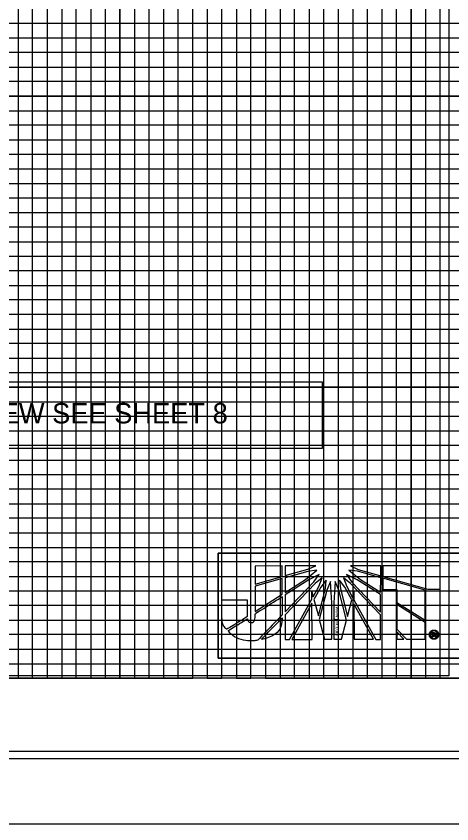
# Model space of a CAD drawing. Extents: x 557032 to 558716, y 525869 to 526969.
# Drawn here: x 558363.8 to 558513.5, y 525869.2 to 526146.7 of the extents above; entities that cross this region are included whole.
import ezdxf

# ---------------------------------------------------------------- set-up
doc = ezdxf.new("R2010")
doc.units = 0
for name, color, linetype in [('Prop VPI Label', 7, 'Continuous'), ('Scratch_Level_5', 7, 'Continuous'), ('Sheet Cutting Line CELL', 7, 'Continuous'), ('Sheet DOT Grid CELL', 7, 'Continuous'), ('Sheet Layout Profile Border Port 2', 7, 'Continuous'), ('Sheet Plot Border Inside CELL', 7, 'Continuous'), ('Sheet Plot Border Outside CELL', 7, 'Continuous'), ('Sheet Profile CELL', 7, 'Continuous'), ('Sheet Profile Grid Major CELL', 7, 'Continuous'), ('Sheet Profile Grid Middle CELL', 7, 'Continuous'), ('Sheet Profile Grid Minor CELL', 7, 'Continuous')]:
    doc.layers.add(name, color=color, linetype=linetype)

msp = doc.modelspace()

# ---------------------------------------------------------------- linework, layer by layer
at = {"layer": 'Prop VPI Label'}
for p, q in [((558455.21, 525957.82), (558445.85, 525957.81)), ((558445.85, 525957.81), (558445.85, 525951.6)), ((558455.21, 525954.21), (558455.21, 525957.82)), ((558466.72, 525957.88), (558456.18, 525957.87)), ((558456.18, 525957.87), (558456.19, 525954.51)), ((558464.03, 525956.69), (558466.72, 525957.88)), ((558489.02, 525957.85), (558478.64, 525957.89)), ((558478.64, 525957.89), (558481.27, 525956.66)), ((558489.03, 525954.48), (558489.02, 525957.85)), ((558509.43, 525957.92), (558489.75, 525957.9)), ((558489.75, 525957.9), (558489.75, 525954.28)), ((558509.44, 525949.85), (558509.43, 525957.92)), ((558445.85, 525951.6), (558455.21, 525954.21)), ((558456.19, 525954.51), (558464.03, 525956.69)), ((558464.03, 525955.96), (558456.19, 525953.79)), ((558463.22, 525953.18), (558467.09, 525956.33)), ((558467.09, 525956.33), (558464.03, 525955.96)), ((558467.86, 525954.88), (558464.3, 525953.07)), ((558466.06, 525952.35), (558467.86, 525954.88)), ((558477.3, 525954.89), (558479.11, 525952.31)), ((558480.92, 525953.09), (558477.3, 525954.89)), ((558478.12, 525956.34), (558482.05, 525953.13)), ((558481.01, 525955.98), (558478.12, 525956.34)), ((558489.03, 525953.77), (558481.01, 525955.98)), ((558481.27, 525956.66), (558489.03, 525954.48)), ((558489.75, 525954.28), (558489.75, 525954.18)), ((558489.75, 525954.18), (558505.25, 525949.85)), ((558455.21, 525953.53), (558445.85, 525950.89)), ((558455.22, 525948.1), (558455.21, 525953.53)), ((558456.19, 525953.79), (558456.19, 525948.72)), ((558456.19, 525948.72), (558463.22, 525953.18)), ((558464.3, 525953.07), (558456.19, 525947.9)), ((558456.2, 525942.06), (558466.06, 525952.35)), ((558466.46, 525951.84), (558456.2, 525941.08)), ((558468.95, 525953.75), (558466.46, 525951.84)), ((558467.81, 525950.76), (558468.95, 525953.75)), ((558470.29, 525952.92), (558468.44, 525950.54)), ((558470.03, 525950.03), (558470.29, 525952.92)), ((558471.84, 525952.51), (558470.56, 525949.51)), ((558472.24, 525945.12), (558471.84, 525952.51)), ((558473.38, 525952.51), (558472.91, 525945.12)), ((558474.62, 525949.51), (558473.38, 525952.51)), ((558474.88, 525952.93), (558475.19, 525949.93)), ((558476.69, 525950.55), (558474.88, 525952.93)), ((558476.21, 525953.76), (558477.35, 525950.77)), ((558478.7, 525951.85), (558476.21, 525953.76)), ((558488.98, 525941.01), (558478.7, 525951.85)), ((558479.11, 525952.31), (558488.98, 525941.99)), ((558488.97, 525947.98), (558480.92, 525953.09)), ((558482.05, 525953.13), (558488.97, 525948.82)), ((558488.97, 525948.82), (558489.03, 525953.77)), ((558489.75, 525953.62), (558489.75, 525953.56)), ((558504.26, 525949.49), (558489.75, 525953.62)), ((558489.75, 525953.56), (558489.76, 525949.79)), ((558445.85, 525950.89), (558445.86, 525942.16)), ((558465.38, 525946.41), (558465.38, 525948.89)), ((558465.38, 525948.89), (558465.85, 525947.19)), ((558465.85, 525947.19), (558467.81, 525950.76)), ((558468.44, 525950.54), (558466.11, 525946.31)), ((558467.61, 525940.68), (558470.03, 525950.03)), ((558470.56, 525949.51), (558467.92, 525939.39)), ((558477.32, 525939.24), (558474.62, 525949.51)), ((558475.19, 525949.93), (558477.62, 525940.48)), ((558479.12, 525946.16), (558476.69, 525950.55)), ((558477.35, 525950.77), (558479.36, 525947.04)), ((558479.36, 525947.04), (558479.84, 525948.9)), ((558479.84, 525948.9), (558479.84, 525946.16)), ((558489.76, 525949.79), (558494.56, 525949.79)), ((558494.56, 525949.79), (558494.57, 525945.3)), ((558504.27, 525939.16), (558504.26, 525949.49)), ((558505.25, 525949.85), (558509.44, 525949.85)), ((558445.86, 525942.16), (558455.22, 525948.1)), ((558456.19, 525947.9), (558456.2, 525942.06)), ((558457.75, 525932.58), (558465.38, 525946.41)), ((558466.11, 525946.31), (558467.61, 525940.68)), ((558477.62, 525940.48), (558479.12, 525946.16)), ((558479.84, 525946.16), (558487.33, 525932.61)), ((558488.98, 525941.99), (558488.97, 525947.98)), ((558465.39, 525945.07), (558458.48, 525932.58)), ((558465.46, 525932.59), (558465.39, 525945.07)), ((558472.26, 525932.64), (558472.24, 525945.12)), ((558472.91, 525945.12), (558472.92, 525932.64)), ((558486.56, 525932.65), (558479.85, 525944.82)), ((558479.85, 525944.82), (558479.86, 525932.65)), ((558494.57, 525945.3), (558504.27, 525939.16)), ((558494.57, 525944.53), (558494.58, 525936.15)), ((558504.27, 525938.43), (558494.57, 525944.53)), ((558456.2, 525941.08), (558456.21, 525932.58)), ((558488.99, 525932.61), (558488.98, 525941.01)), ((558467.92, 525939.39), (558469.69, 525932.64)), ((558475.52, 525932.64), (558477.32, 525939.24)), ((558504.28, 525932.63), (558504.27, 525938.43)), ((558494.58, 525936.15), (558497.93, 525932.62)), ((558497, 525932.62), (558494.58, 525935.24)), ((558494.58, 525935.24), (558494.58, 525932.62)), ((558506.74, 525933.51), (558506.74, 525934.94)), ((558506.74, 525934.94), (558507.33, 525934.94)), ((558507.33, 525934.67), (558507.07, 525934.67)), ((558507.07, 525934.67), (558507.07, 525934.33)), ((558507.33, 525935.79), (558507.33, 525935.49)), ((558507.33, 525935.49), (558507.33, 525935.79)), ((558507.33, 525934.94), (558507.33, 525934.67)), ((558507.33, 525934.67), (558507.33, 525934.94)), ((558507.33, 525934.94), (558507.42, 525934.94)), ((558507.37, 525934.67), (558507.33, 525934.67)), ((558456.21, 525932.58), (558457.75, 525932.58)), ((558458.48, 525932.58), (558465.46, 525932.59)), ((558469.69, 525932.64), (558472.26, 525932.64)), ((558472.92, 525932.64), (558475.52, 525932.64)), ((558479.86, 525932.65), (558486.56, 525932.65)), ((558487.33, 525932.61), (558488.99, 525932.61)), ((558494.58, 525932.62), (558497, 525932.62)), ((558497.93, 525932.62), (558504.28, 525932.63)), ((558507.07, 525933.51), (558506.74, 525933.51)), ((558507.07, 525934.33), (558507.33, 525934.33)), ((558507.33, 525934.07), (558507.07, 525934.07)), ((558507.07, 525934.07), (558507.07, 525933.51)), ((558507.33, 525934.33), (558507.33, 525934.07)), ((558507.33, 525934.07), (558507.33, 525934.33)), ((558507.33, 525934.33), (558507.34, 525934.33)), ((558507.34, 525934.07), (558507.33, 525934.07)), ((558507.33, 525932.95), (558507.33, 525932.64)), ((558507.33, 525932.64), (558507.33, 525932.95)), ((558507.33, 525932.95), (558507.34, 525932.95)), ((558507.34, 525932.64), (558507.33, 525932.64))]:
    msp.add_line(p, q, dxfattribs=at)
for points in [[(558297.78, 526021.14), (558468.92, 526021.14), (558468.92, 525998.23), (558297.78, 525998.23)], [(558297.78, 526021.14), (558468.92, 526021.14), (558468.92, 525998.23), (558297.78, 525998.23)], [(558433.19, 525962.24), (558633.22, 525962.24), (558633.22, 525926.14), (558433.19, 525926.14)], [(558433.19, 525926.14), (558633.22, 525926.14), (558633.22, 525962.24), (558433.19, 525962.24)]]:
    msp.add_lwpolyline(points, close=True, dxfattribs=at)
for points in [[(558445.85, 525951.6), (558455.21, 525954.21), (558455.21, 525957.82), (558445.85, 525957.81), (558445.85, 525951.6)], [(558464.03, 525956.69), (558466.72, 525957.88), (558456.18, 525957.87), (558456.19, 525954.51), (558464.03, 525956.69)], [(558481.27, 525956.66), (558489.03, 525954.48), (558489.02, 525957.85), (558478.64, 525957.89), (558481.27, 525956.66)], [(558509.43, 525957.92), (558489.75, 525957.9), (558489.75, 525954.28), (558489.75, 525954.18), (558505.25, 525949.85), (558509.44, 525949.85), (558509.43, 525957.92)], [(558456.19, 525953.79), (558456.19, 525948.72), (558463.22, 525953.18), (558467.09, 525956.33), (558464.03, 525955.96), (558456.19, 525953.79)], [(558456.19, 525947.9), (558456.2, 525942.06), (558466.06, 525952.35), (558467.86, 525954.88), (558464.3, 525953.07), (558456.19, 525947.9)], [(558477.3, 525954.89), (558479.11, 525952.31), (558488.98, 525941.99), (558488.97, 525947.98), (558480.92, 525953.09), (558477.3, 525954.89)], [(558478.12, 525956.34), (558482.05, 525953.13), (558488.97, 525948.82), (558489.03, 525953.77), (558481.01, 525955.98), (558478.12, 525956.34)], [(558445.86, 525942.16), (558455.22, 525948.1), (558455.21, 525953.53), (558445.85, 525950.89), (558445.86, 525942.16)], [(558468.95, 525953.75), (558466.46, 525951.84), (558456.2, 525941.08), (558456.21, 525932.58), (558457.75, 525932.58), (558465.38, 525946.41), (558465.38, 525948.89), (558465.85, 525947.19), (558467.81, 525950.76), (558468.95, 525953.75)], [(558470.29, 525952.92), (558468.44, 525950.54), (558466.11, 525946.31), (558467.61, 525940.68), (558470.03, 525950.03), (558470.29, 525952.92)], [(558470.56, 525949.51), (558467.92, 525939.39), (558469.69, 525932.64), (558472.26, 525932.64), (558472.24, 525945.12), (558471.84, 525952.51), (558470.56, 525949.51)], [(558473.38, 525952.51), (558472.91, 525945.12), (558472.92, 525932.64), (558475.52, 525932.64), (558477.32, 525939.24), (558474.62, 525949.51), (558473.38, 525952.51)], [(558474.88, 525952.93), (558475.19, 525949.93), (558477.62, 525940.48), (558479.12, 525946.16), (558476.69, 525950.55), (558474.88, 525952.93)], [(558476.21, 525953.76), (558477.35, 525950.77), (558479.36, 525947.04), (558479.84, 525948.9), (558479.84, 525946.16), (558487.33, 525932.61), (558488.99, 525932.61), (558488.98, 525941.01), (558478.7, 525951.85), (558476.21, 525953.76)], [(558489.75, 525953.62), (558489.75, 525953.56), (558489.76, 525949.79), (558494.56, 525949.79), (558494.57, 525945.3), (558504.27, 525939.16), (558504.26, 525949.49), (558489.75, 525953.62)], [(558458.48, 525932.58), (558465.46, 525932.59), (558465.39, 525945.07), (558458.48, 525932.58)], [(558479.86, 525932.65), (558486.56, 525932.65), (558479.85, 525944.82), (558479.86, 525932.65)], [(558494.57, 525944.53), (558494.58, 525936.15), (558497.93, 525932.62), (558504.28, 525932.63), (558504.27, 525938.43), (558494.57, 525944.53), (558494.57, 525944.53)], [(558494.58, 525932.62), (558494.58, 525932.62), (558497, 525932.62), (558494.58, 525935.24), (558494.58, 525932.62)], [(558507.95, 525933.85), (558507.95, 525933.77), (558507.97, 525933.72), (558507.97, 525933.67), (558508.01, 525933.51), (558507.71, 525933.51)]]:
    msp.add_lwpolyline(points, dxfattribs=at)
for points, degree in [([(558443.17, 525946.18), (558443.17, 525946.18), (558434.51, 525946.17), (558434.51, 525946.17), (558434.51, 525946.17), (558434.51, 525940.75), (558434.51, 525940.75), (558434.51, 525940.75), (558434.51, 525940.17), (558434.51, 525940.17), (558434.51, 525938.48), (558435.07, 525937.13), (558436.06, 525936), (558436.06, 525936), (558443.18, 525940.34), (558443.18, 525940.45), (558443.18, 525940.45), (558443.17, 525946.18), (558443.17, 525946.18)], 3), ([(558444.52, 525938.38), (558443.97, 525938.38), (558443.49, 525938.68), (558443.29, 525939.72), (558443.29, 525939.72), (558436.57, 525935.56), (558436.57, 525935.56), (558438.64, 525933.38), (558441.95, 525932.09), (558444.75, 525932.09), (558445.47, 525932.09), (558446.03, 525932.15), (558446.8, 525932.31), (558446.8, 525932.31), (558455.23, 525941.03), (558455.23, 525941.03), (558455.23, 525941.03), (558455.22, 525947.33), (558455.22, 525947.33), (558455.22, 525947.33), (558445.86, 525941.37), (558445.86, 525941.37), (558445.87, 525939.01), (558445.3, 525938.38), (558444.52, 525938.38)], 3), ([(558444.52, 525938.38), (558443.97, 525938.38), (558443.49, 525938.68), (558443.29, 525939.72), (558443.29, 525939.72), (558436.57, 525935.56), (558436.57, 525935.56), (558438.64, 525933.38), (558441.95, 525932.09), (558444.75, 525932.09), (558445.47, 525932.09), (558446.03, 525932.15), (558446.8, 525932.31), (558446.8, 525932.31), (558455.23, 525941.03), (558455.23, 525941.03), (558455.23, 525941.03), (558455.22, 525947.33), (558455.22, 525947.33), (558455.22, 525947.33), (558445.86, 525941.37), (558445.86, 525941.37), (558445.87, 525939.01), (558445.3, 525938.38), (558444.52, 525938.38)], 3), ([(558455.23, 525940.04), (558455.23, 525940.04), (558447.94, 525932.51), (558447.94, 525932.51), (558451.51, 525933.39), (558455.06, 525935.76), (558455.23, 525940.04)], 3), ([(558507.33, 525932.64), (558506.9, 525932.64), (558506.52, 525932.8), (558506.21, 525933.11), (558505.9, 525933.41), (558505.74, 525933.78), (558505.74, 525934.23), (558505.74, 525934.67), (558505.9, 525935.05), (558506.21, 525935.33), (558506.52, 525935.63), (558506.88, 525935.79), (558507.33, 525935.79)], 3), ([(558507.33, 525935.49), (558506.98, 525935.49), (558506.68, 525935.37), (558506.43, 525935.14), (558506.18, 525934.89), (558506.05, 525934.58), (558506.05, 525934.23), (558506.05, 525933.87), (558506.18, 525933.56), (558506.43, 525933.32), (558506.68, 525933.07), (558506.98, 525932.95), (558507.33, 525932.95)], 3), ([(558507.33, 525935.79), (558507.77, 525935.79), (558508.15, 525935.63), (558508.46, 525935.33), (558508.77, 525935.05), (558508.93, 525934.67), (558508.93, 525934.23)], 3), ([(558507.34, 525932.95), (558507.69, 525932.95), (558507.99, 525933.07), (558508.24, 525933.32), (558508.49, 525933.56), (558508.62, 525933.88), (558508.62, 525934.23), (558508.62, 525934.58), (558508.49, 525934.89), (558508.24, 525935.14), (558507.99, 525935.37), (558507.69, 525935.49), (558507.33, 525935.49)], 3), ([(558507.34, 525934.33), (558507.55, 525934.33), (558507.65, 525934.4), (558507.65, 525934.51), (558507.65, 525934.62), (558507.56, 525934.67), (558507.37, 525934.67)], 3), ([(558507.42, 525934.94), (558507.78, 525934.94), (558507.97, 525934.8), (558507.97, 525934.51), (558507.97, 525934.38), (558507.91, 525934.28), (558507.8, 525934.2)], 3), ([(558508.93, 525934.23), (558508.93, 525933.79), (558508.77, 525933.41), (558508.47, 525933.1), (558508.16, 525932.8), (558507.79, 525932.64), (558507.34, 525932.64)], 3), ([(558507.59, 525934.02), (558507.55, 525934.05), (558507.47, 525934.07), (558507.34, 525934.07)], 2), ([(558507.71, 525933.51), (558507.67, 525933.59), (558507.64, 525933.67), (558507.64, 525933.77), (558507.64, 525933.9), (558507.63, 525933.98), (558507.59, 525934.02)], 3), ([(558507.8, 525934.2), (558507.89, 525934.15), (558507.94, 525934.03), (558507.95, 525933.85)], 2)]:
    msp.add_open_spline(points, degree=degree, dxfattribs=at)
at = {"layer": 'Scratch_Level_5'}
msp.add_lwpolyline([(557997.44, 526420.09), (558512.44, 526420.09), (558512.49, 525920.09), (557997.49, 525920.09)], close=True, dxfattribs=at)
at = {"layer": 'Sheet Cutting Line CELL'}
msp.add_line((557032.45, 525869.22), (558716.45, 525869.22), dxfattribs=at)
at = {"layer": 'Sheet DOT Grid CELL'}
for p, q in [((558399.45, 526419.22), (558399.45, 525919.22)), ((558449.45, 526419.22), (558449.45, 525919.22)), ((558499.45, 526419.22), (558499.45, 525919.22)), ((557199.45, 526119.22), (558699.34, 526119.22)), ((557199.45, 526069.22), (558699.34, 526069.22)), ((557199.45, 526019.22), (558699.34, 526019.22)), ((557199.45, 525969.22), (558699.34, 525969.22))]:
    msp.add_line(p, q, dxfattribs=at)
at = {"layer": 'Sheet Layout Profile Border Port 2'}
msp.add_lwpolyline([(557249.45, 526419.22), (558649.45, 526419.22), (558649.45, 525919.22), (557249.45, 525919.22)], close=True, dxfattribs=at)
at = {"layer": 'Sheet Plot Border Inside CELL'}
msp.add_lwpolyline([(557045.45, 525891.67), (558711.95, 525891.67), (558711.95, 526946.77), (557045.45, 526946.77)], close=True, dxfattribs=at)
at = {"layer": 'Sheet Plot Border Outside CELL'}
msp.add_lwpolyline([(557032.45, 525869.22), (558716.45, 525869.22), (558716.45, 526969.22), (557032.45, 526969.22)], close=True, dxfattribs=at)
at = {"layer": 'Sheet Profile CELL'}
for p, q in [((558699.45, 525919.22), (557199.45, 525919.22)), ((557199.45, 525894.22), (558699.45, 525894.22))]:
    msp.add_line(p, q, dxfattribs=at)
msp.add_lwpolyline([(558699.45, 526944.22), (557199.45, 526944.22), (557199.45, 525894.22), (558699.45, 525894.22)], close=True, dxfattribs=at)
at = {"layer": 'Sheet Profile Grid Major CELL'}
for points in [[(558349.45, 525919.22), (558399.45, 525919.22), (558399.45, 526419.22), (558449.45, 526419.22), (558449.45, 525919.22), (558499.45, 525919.22), (558499.45, 526419.22), (558549.45, 526419.22), (558549.45, 526047.76)], [(558699.45, 526119.22), (557199.45, 526119.22), (557199.45, 526069.22), (558699.45, 526069.22)], [(558699.45, 526019.22), (557199.45, 526019.22), (557199.45, 526019.22), (557199.45, 525969.22), (558699.45, 525969.22)], [(558699.45, 525919.22), (557199.45, 525919.22)]]:
    msp.add_lwpolyline(points, dxfattribs=at)
at = {"layer": 'Sheet Profile Grid Middle CELL'}
for points in [[(558324.45, 526419.22), (558374.45, 526419.22), (558374.45, 525919.22), (558424.45, 525919.22), (558424.45, 526419.22), (558474.45, 526419.22), (558474.45, 525919.22), (558524.45, 525919.22), (558524.45, 526419.22), (558574.45, 526419.22), (558574.45, 526047.76)], [(558699.45, 526144.22), (557199.45, 526144.22), (557199.45, 526094.22), (558699.45, 526094.22)], [(558546.09, 526044.22), (557199.45, 526044.22), (557199.45, 525994.22), (558699.45, 525994.22)], [(558699.45, 525944.22), (557199.45, 525944.22)]]:
    msp.add_lwpolyline(points, dxfattribs=at)
at = {"layer": 'Sheet Profile Grid Minor CELL'}
for p, q in [((557249.45, 526139.22), (558649.45, 526139.22)), ((558649.45, 526134.22), (557249.45, 526134.22)), ((557249.45, 526129.22), (558649.45, 526129.22)), ((558649.45, 526124.22), (557249.45, 526124.22)), ((557249.45, 526114.22), (558649.45, 526114.22)), ((558649.45, 526109.22), (557249.45, 526109.22)), ((557249.45, 526104.22), (558649.45, 526104.22)), ((558649.45, 526099.22), (557249.45, 526099.22)), ((557249.45, 526089.22), (558649.45, 526089.22)), ((558649.45, 526084.22), (557249.45, 526084.22)), ((557249.45, 526079.22), (558649.45, 526079.22)), ((558649.45, 526074.22), (557249.45, 526074.22)), ((557249.45, 526064.22), (558649.45, 526064.22)), ((558649.45, 526059.22), (557249.45, 526059.22)), ((557249.45, 526054.22), (558649.45, 526054.22)), ((558649.45, 526049.22), (557249.45, 526049.22)), ((557249.45, 526039.22), (558546.09, 526039.22)), ((558546.09, 526034.22), (557249.45, 526034.22)), ((557249.45, 526029.22), (558546.09, 526029.22)), ((558546.09, 526024.22), (557249.45, 526024.22)), ((557249.45, 526014.22), (558649.45, 526014.22)), ((558649.45, 526009.22), (557249.45, 526009.22)), ((557249.45, 526004.22), (558649.45, 526004.22)), ((558649.45, 525999.22), (557249.45, 525999.22)), ((557249.45, 525989.22), (558649.45, 525989.22)), ((558649.45, 525984.22), (557249.45, 525984.22)), ((557249.45, 525979.22), (558649.45, 525979.22)), ((558649.45, 525974.22), (557249.45, 525974.22)), ((557249.45, 525964.22), (558649.45, 525964.22)), ((558649.45, 525959.22), (557249.45, 525959.22)), ((557249.45, 525954.22), (558649.45, 525954.22)), ((558649.45, 525949.22), (557249.45, 525949.22)), ((557249.45, 525939.22), (558649.45, 525939.22)), ((558649.45, 525934.22), (557249.45, 525934.22)), ((557249.45, 525929.22), (558649.45, 525929.22)), ((557249.45, 525924.22), (558649.45, 525924.22))]:
    msp.add_line(p, q, dxfattribs=at)
for points in [[(558359.45, 526419.22), (558364.45, 526419.22), (558364.45, 525919.22), (558369.45, 525919.22), (558369.45, 526419.22), (558379.45, 526419.22), (558379.45, 525919.22), (558384.45, 525919.22), (558384.45, 526419.22), (558389.45, 526419.22), (558389.45, 525919.22)], [(558389.45, 525919.22), (558394.45, 525919.22), (558394.45, 526419.22)], [(558404.45, 526419.22), (558404.45, 525919.22), (558409.45, 525919.22), (558409.45, 526419.22)], [(558414.45, 526419.22), (558414.45, 525919.22), (558419.45, 525919.22), (558419.45, 526419.22)], [(558429.45, 526419.22), (558429.45, 525919.22), (558434.45, 525919.22), (558434.45, 526419.22)], [(558439.45, 526419.22), (558439.45, 525919.22), (558444.45, 525919.22), (558444.45, 526419.22)], [(558454.45, 526419.22), (558454.45, 525919.22), (558459.45, 525919.22), (558459.45, 526419.22)], [(558464.45, 526419.22), (558464.45, 525919.22), (558469.45, 525919.22), (558469.45, 526419.22)], [(558479.45, 526419.22), (558479.45, 525919.22), (558484.45, 525919.22), (558484.45, 526419.22)], [(558489.45, 526419.22), (558489.45, 525919.22), (558494.45, 525919.22), (558494.45, 526419.22)], [(558504.45, 526419.22), (558504.45, 525919.22), (558509.45, 525919.22), (558509.45, 526419.22)]]:
    msp.add_lwpolyline(points, dxfattribs=at)

# ---------------------------------------------------------------- texts
at = {"layer": 'Prop VPI Label'}
msp.add_text('FOR PLAN VIEW SEE SHEET 8', height=7, dxfattribs=at).set_placement((558300.21, 526006.79))
msp.add_text('www.jmt.com', height=1.2413, rotation=270, dxfattribs=at).set_placement((558473.54, 525943.85))

doc.saveas('drawing.dxf')
